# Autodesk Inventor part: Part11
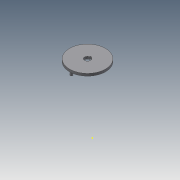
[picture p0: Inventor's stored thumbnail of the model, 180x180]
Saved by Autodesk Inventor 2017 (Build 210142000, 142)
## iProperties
Created: 2019-03
Part Number: Part11
Material: Generic
Document SubType Name: Modeling
Designer: user
Density: 1 g/cm^3
Appearance: Default
Author: user
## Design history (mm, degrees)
sketch "Sketch1"
  geometry: L1 (-284.264, 278.269)-(-284.264, 281.03); L2 (-284.264, 281.03)-(-289.323, 281.03); L3 (-289.323, 281.03)-(-289.323, 278.269); C1 r 75 at (-286.794, 266.027); A1 r 12.5 centre (-286.794, 266.027) between (-289.323, 278.269) and (-284.264, 278.269); 2 further points
  constraints: 6 end point, 2 centre point, 2 point on circle, 1 coincident, 1 midpoint, 1 parallel, 1 vertical alignment
  dimensions: "d0" = 150 diameter of C1; "d1" = 25 diameter of A1
extrude "Extrusion1" new body sketch "Sketch1" distance "d2" = 10; taper "d3" = 0 deg
sketch "Sketch2"
  geometry: 1 further point
sketch "Sketch3"
  geometry: C1 r 5 at (0, -67.353); 1 further point
  constraints: 1 centre point
  dimensions: "d4" = 10 diameter of C1
extrude "Extrusion2" join sketch "Sketch3" distance "d5" = 15; taper "d6" = 0 deg
body "Solid1"
